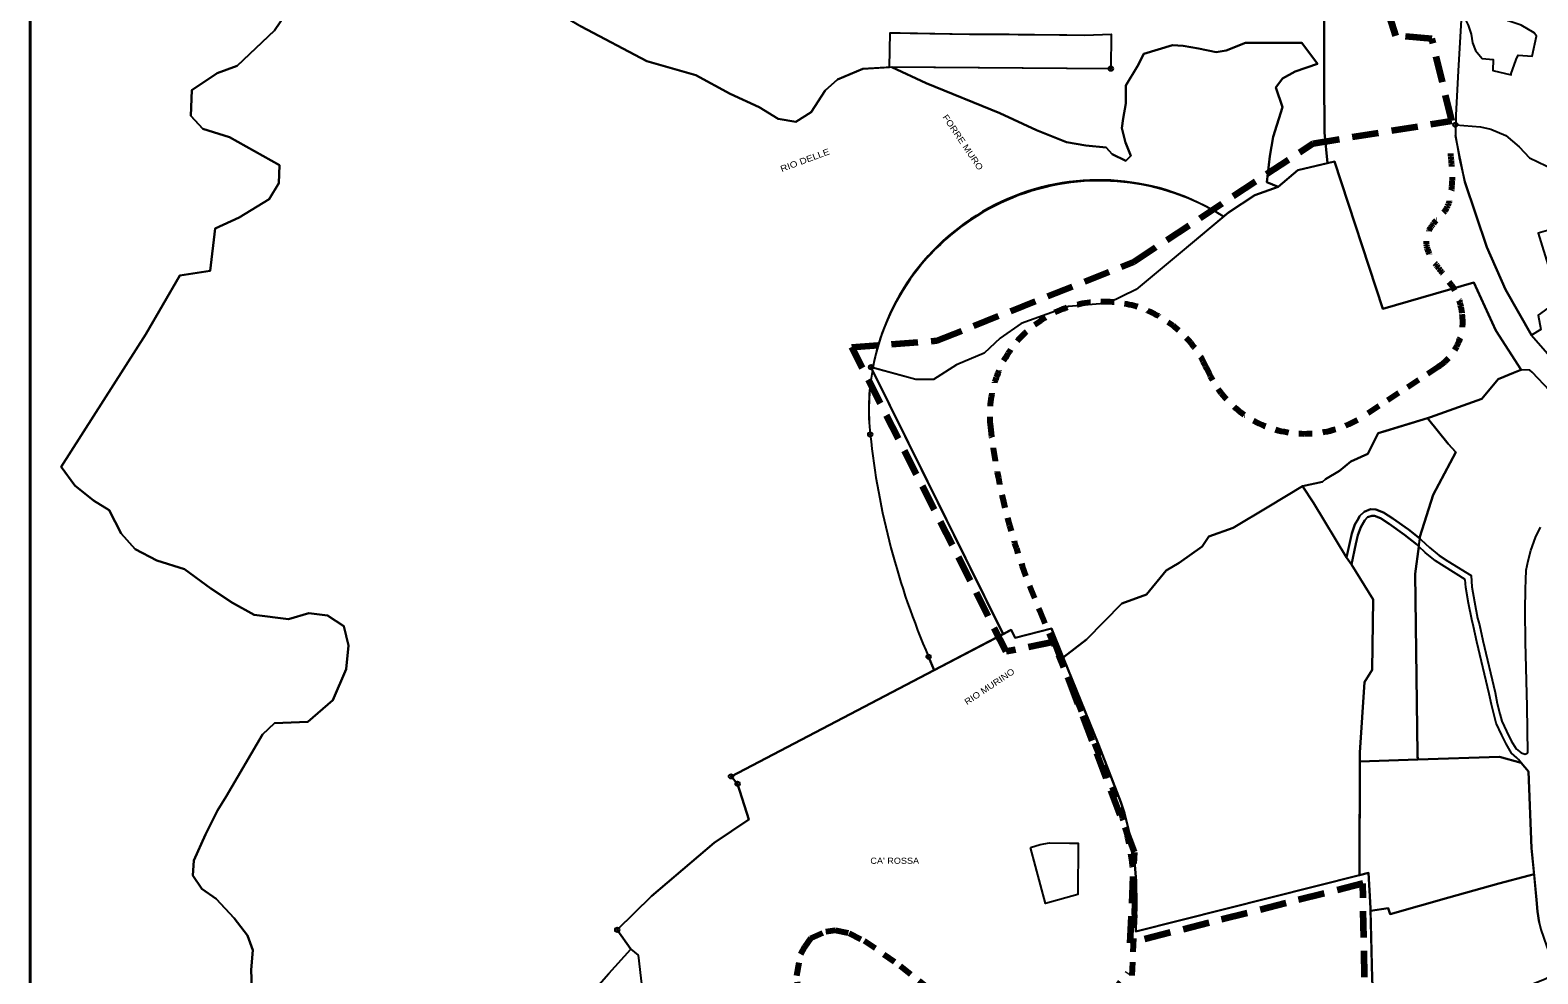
# Model space of a CAD drawing. Extents: x 654952 to 658955, y 890426 to 894481.
# Drawn here: x 657055 to 657738, y 891916 to 892344 of the extents above; entities that cross this region are included whole.
import ezdxf

# ---------------------------------------------------------------- set-up
doc = ezdxf.new("R2010")
doc.units = 0
doc.header["$LTSCALE"] = 4
doc.header["$PDMODE"] = 32
doc.header["$PDSIZE"] = 2
doc.linetypes.add('MEDIUM_DASHED', pattern=[4.5, 3, -1.5])
doc.linetypes.add('SHORT_DASHED', pattern=[2.7, 1.5, -1.2])
for name, color, linetype, lineweight in [('1', 7, 'Continuous', 25), ('12', 7, 'Continuous', 25), ('14', 7, 'Continuous', 25), ('16', 7, 'Continuous', 25), ('18', 7, 'Continuous', 25), ('2', 7, 'Continuous', 25), ('32', 7, 'Continuous', 25), ('35', 7, 'Continuous', 25), ('36', 7, 'Continuous', 25), ('37', 7, 'Continuous', 25), ('41', 7, 'SHORT_DASHED', 80), ('42', 7, 'Continuous', 25), ('43', 7, 'Continuous', 25), ('55', 7, 'Continuous', 25), ('60', 7, 'Continuous', 35), ('7', 7, 'MEDIUM_DASHED', 100), ('9', 7, 'Continuous', 25)]:
    doc.layers.add(name, color=color, linetype=linetype, lineweight=lineweight)
doc.layers.add('58', color=7, linetype='Continuous')

msp = doc.modelspace()

# ---------------------------------------------------------------- linework, layer by layer
at = {"layer": '1'}
for points in [[(657730.31, 892189.89), (657719.89, 892185.61), (657712.47, 892176.68), (657689.22, 892168.43), (657687.88, 892168.02)], [(657743.34, 892180.35), (657735.27, 892188.83), (657734.2, 892189.7), (657730.31, 892189.89)], [(657687.88, 892168.02), (657665.52, 892161.23), (657660.94, 892151.75), (657653.14, 892148.35), (657648.02, 892144.07), (657641.8, 892140.37), (657640.35, 892139.05), (657631.25, 892137.19)], [(657687.88, 892168.02), (657697.26, 892156.31), (657700.7, 892152.54), (657690.55, 892133.19), (657684.5, 892114.14), (657684.4, 892113.38)], [(657684.4, 892113.38), (657684.5, 892114.14), (657690.55, 892133.19), (657700.7, 892152.54), (657697.26, 892156.31), (657687.88, 892168.02)], [(657631.25, 892137.19), (657636.31, 892129.64), (657651.3, 892104.86), (657653.64, 892115.72), (657655, 892119.72), (657656.62, 892122.55), (657657.18, 892123.53)], [(657672.22, 892122.53), (657667.93, 892125.21), (657664.59, 892126.64), (657662.11, 892126.67), (657659.19, 892125.53), (657657.18, 892123.53), (657656.62, 892122.55), (657655, 892119.72), (657653.64, 892115.72), (657651.3, 892104.86), (657653.54, 892101.61)], [(657657.18, 892123.53), (657659.19, 892125.53), (657662.11, 892126.67), (657664.59, 892126.64), (657667.93, 892125.21), (657672.22, 892122.53)], [(657653.54, 892101.61), (657655.49, 892111.05), (657656.44, 892114.9), (657657.67, 892118.52), (657659.51, 892121.74), (657660.81, 892123.04), (657662.64, 892123.75), (657663.98, 892123.74), (657666.58, 892122.62), (657670.61, 892120.11), (657677.56, 892115.18), (657683.14, 892110.66)], [(657672.22, 892122.53), (657679.32, 892117.5), (657684.4, 892113.38)], [(657684.4, 892113.38), (657679.32, 892117.5), (657672.22, 892122.53)], [(657733.42, 892016.41), (657733, 892037.31), (657732.37, 892066.45), (657732.21, 892080.97), (657732.29, 892090.51), (657732.44, 892094.7), (657732.67, 892099.17), (657733.53, 892103.35), (657734.73, 892108.04), (657736.87, 892113.86), (657739.08, 892118.64)], [(657683.14, 892110.66), (657683.96, 892109.9), (657684.4, 892113.38)], [(657684.4, 892113.38), (657685.04, 892112.86), (657688.85, 892109.36), (657693.25, 892105.74), (657697.15, 892103.21), (657707.63, 892096.65), (657707.93, 892091.51)], [(657707.93, 892091.51), (657709.15, 892084.7), (657710.61, 892077.33), (657711.41, 892074.27), (657712.98, 892067.32)], [(657712.98, 892067.32), (657718.58, 892043.66), (657719.49, 892038.78), (657720.74, 892034.1), (657721.54, 892030.67), (657723.63, 892026.19), (657725.88, 892021.79), (657728.09, 892018.11), (657730.39, 892016.38), (657732.08, 892015.83), (657733.42, 892016.41)]]:
    msp.add_lwpolyline(points, dxfattribs=at)
at = {"layer": '12'}
for points in [[(657730.39, 892011.9), (657720.46, 892014.5), (657683.5, 892013.34), (657657.23, 892012.51), (657657.2, 891961.01), (657661.2, 891962.02), (657662.06, 891946.06), (657662.1, 891944.72)], [(657662.1, 891944.72), (657670.04, 891946.05), (657670.95, 891943.35), (657697.64, 891950.84), (657720.22, 891957.11), (657733.98, 891960.82), (657736.18, 891961.41), (657735.02, 891973.19), (657733.61, 892007.87), (657730.39, 892011.9)], [(657736.18, 891961.41), (657733.98, 891960.82), (657720.22, 891957.11), (657697.64, 891950.84), (657670.95, 891943.35), (657670.04, 891946.05), (657662.1, 891944.72)], [(657738.45, 891939.43), (657737.71, 891944.48), (657737.33, 891949.76), (657736.18, 891961.41)], [(657662.1, 891944.72), (657662.89, 891914.18), (657664.35, 891883.16), (657680.65, 891889.73), (657700.14, 891897.46)]]:
    msp.add_lwpolyline(points, dxfattribs=at)
at = {"layer": '14'}
msp.add_line((657720.46, 892014.5), (657730.39, 892011.9), dxfattribs=at)
for points in [[(657683.96, 892109.9), (657683.14, 892110.66), (657677.56, 892115.18), (657670.61, 892120.11), (657666.58, 892122.62), (657663.98, 892123.74), (657662.64, 892123.75), (657660.81, 892123.04), (657659.51, 892121.74), (657657.67, 892118.52), (657656.44, 892114.9), (657655.49, 892111.05), (657653.54, 892101.61), (657663.25, 892085.79), (657662.83, 892053.9), (657659.41, 892048.34), (657657.23, 892016.51), (657657.23, 892012.51), (657683.5, 892013.34)], [(657683.96, 892109.9), (657682.4, 892097.52), (657683.43, 892015.78), (657683.46, 892014.56), (657683.5, 892013.34), (657720.46, 892014.5)], [(657683.5, 892013.34), (657683.46, 892014.56), (657683.43, 892015.78), (657682.4, 892097.52), (657683.96, 892109.9)], [(657705, 892094.85), (657695.58, 892100.75), (657691.53, 892103.39), (657686.94, 892107.16), (657683.96, 892109.9)], [(657730.39, 892011.9), (657729.2, 892013.39), (657728.43, 892014.15), (657726.02, 892016.25), (657723.49, 892020.47), (657721.54, 892024.31), (657718.95, 892029.76), (657718.09, 892033.44), (657716.83, 892038.18), (657715.91, 892043.1), (657710.32, 892066.71), (657708.76, 892073.62), (657707.95, 892076.72), (657706.47, 892084.19), (657705.22, 892091.19), (657705, 892094.85)]]:
    msp.add_lwpolyline(points, dxfattribs=at)
at = {"layer": '16'}
msp.add_line((657648.03, 892144.07), (657653.14, 892148.35), dxfattribs=at)
for points in [[(657730.31, 892189.89), (657718.91, 892207.73), (657708.94, 892229.37), (657667.72, 892217.43), (657645.77, 892284.29), (657629.16, 892280.28), (657620.25, 892272.73), (657609.75, 892268.92), (657597.75, 892261.11), (657575.85, 892242.89), (657556.07, 892226.25), (657543.34, 892220.08), (657525.41, 892218.48), (657503.89, 892210.78), (657494.35, 892204.27), (657487.14, 892197.46), (657474.62, 892192.13), (657464.29, 892185.5), (657456.3, 892185.51), (657435.92, 892191.02), (657495.83, 892070.17), (657499.37, 892072.03), (657501.16, 892068.44), (657517.67, 892072.7), (657523, 892059.5), (657533.55, 892067.71)], [(657687.88, 892168.01), (657689.22, 892168.43), (657712.47, 892176.68), (657719.89, 892185.61), (657726.79, 892188.45), (657729.83, 892189.69), (657730.31, 892189.89)], [(657653.14, 892148.35), (657660.94, 892151.75), (657665.52, 892161.23), (657687.88, 892168.02)], [(657687.88, 892168.01), (657687.88, 892168.02), (657665.52, 892161.23)], [(657665.52, 892161.23), (657669.19, 892162.16), (657687.88, 892168.01)], [(657533.55, 892067.71), (657549.56, 892083.97), (657560.65, 892088.04), (657569.61, 892099.03), (657575.43, 892102.47), (657585.94, 892109.88), (657588.88, 892114.41), (657599.93, 892118.21), (657616.11, 892127.89), (657631.25, 892137.19), (657640.35, 892139.05)], [(657640.35, 892139.05), (657641.8, 892140.37), (657648.02, 892144.07)], [(657631.25, 892137.19), (657616.11, 892127.89), (657599.93, 892118.21), (657588.88, 892114.41), (657585.94, 892109.88), (657575.43, 892102.47), (657569.61, 892099.03), (657560.65, 892088.04), (657549.56, 892083.97), (657533.55, 892067.71), (657523, 892059.5)], [(657657.2, 891961.01), (657657.23, 892016.51), (657659.41, 892048.34), (657662.83, 892053.9), (657663.26, 892085.79), (657653.54, 892101.61), (657651.3, 892104.86), (657636.31, 892129.64), (657631.25, 892137.19)], [(657523, 892059.5), (657538.92, 892020.11), (657549.05, 891994.02), (657550.72, 891989.05), (657552.37, 891982.35), (657554.39, 891973.09), (657555.19, 891967.45), (657555.96, 891958.26), (657556.12, 891947.47), (657555.83, 891935.5), (657657.2, 891961.01)]]:
    msp.add_lwpolyline(points, dxfattribs=at)
at = {"layer": '18'}
for points in [[(657544.51, 892326.27), (657544.51, 892326.27), (657444.35, 892326.94), (657444.6, 892342.44)], [(657444.6, 892342.44), (657449.13, 892342.44), (657480.5, 892341.94), (657498.5, 892341.94), (657532.75, 892341.44), (657544.73, 892341.91), (657544.51, 892326.27)]]:
    msp.add_lwpolyline(points, dxfattribs=at)
msp.add_point((657544.51, 892326.27), dxfattribs=at)
at = {"layer": '2'}
msp.add_lwpolyline([(657508.14, 891973.49), (657512.53, 891974.91), (657516.71, 891975.52), (657525.85, 891975.44), (657529.78, 891975.4), (657529.57, 891952.22), (657515, 891948.05)], close=True, dxfattribs=at)
at = {"layer": '32'}
for points in [[(657499.37, 892072.03), (657495.87, 892070.2), (657372.54, 892005.7), (657375.54, 892002.31), (657380.61, 891986.11), (657364.98, 891975.6), (657336.53, 891951.39), (657321.01, 891936.2), (657327.2, 891927.48), (657330.48, 891924.75), (657333.71, 891897.41)], [(657657.2, 891961.01), (657555.83, 891935.5), (657556.12, 891947.47), (657555.96, 891958.26), (657555.19, 891967.45), (657554.39, 891973.09), (657552.37, 891982.35), (657550.72, 891989.05), (657549.05, 891994.02), (657538.92, 892020.11), (657517.67, 892072.7), (657501.16, 892068.44), (657499.37, 892072.03)], [(657680.65, 891889.73), (657680.65, 891889.73), (657664.35, 891883.16), (657662.89, 891914.18), (657662.06, 891946.06), (657661.2, 891962.02), (657657.2, 891961.01)]]:
    msp.add_lwpolyline(points, dxfattribs=at)
at = {"layer": '35'}
msp.add_lwpolyline([(657333.71, 891897.41), (657331.73, 891853.22), (657356.3, 891845.74), (657368.76, 891841.68), (657396.27, 891828.43), (657328.24, 891714.82), (657314.28, 891707.1), (657284.74, 891693.21), (657234.36, 891722), (657211.1, 891732.13), (657198.81, 891740.15), (657211.6, 891767.49), (657221.37, 891781.04), (657236.78, 891798.07), (657250.85, 891807.99), (657281.25, 891827.07), (657299.59, 891838.23), (657313.17, 891849.32), (657311.41, 891867.55), (657311.06, 891883.8), (657310.62, 891908.79), (657317.2, 891916.42), (657327.2, 891927.48), (657330.48, 891924.75)], close=True, dxfattribs=at)
at = {"layer": '36'}
for p, q in [((657436.55, 892189.74), (657435.96, 892191.05)), ((657375.53, 892002.31), (657372.54, 892005.7))]:
    msp.add_line(p, q, dxfattribs=at)
for points in [[(657183.78, 892370.19), (657165.83, 892343.58), (657148.87, 892327.61), (657139.89, 892324.23), (657128.42, 892316.49), (657127.92, 892304.87), (657133.41, 892299.07), (657145.38, 892295.2), (657168.06, 892282.53), (657167.79, 892274.35), (657163.34, 892267.13), (657149.87, 892258.91), (657138.92, 892253.91), (657136.67, 892234.74), (657122.96, 892232.62), (657107.49, 892206.01), (657069.15, 892145.94), (657075.42, 892137.49), (657083.86, 892130.68), (657090.95, 892126.31), (657096.4, 892115.68), (657102.66, 892108.59), (657112.47, 892103.41), (657125, 892099.59), (657136.99, 892090.86), (657146.8, 892084.32), (657156.61, 892078.87), (657172.14, 892076.96), (657181.4, 892079.69), (657189.85, 892078.6), (657197.21, 892073.69), (657199.39, 892064.96)], [(657551.31, 892310.56), (657550.05, 892303.77), (657549.54, 892299.3), (657551.22, 892292.76), (657553.62, 892286.83), (657551.25, 892284.56), (657545.19, 892287.54), (657542.43, 892290.55), (657533.22, 892291.46), (657524.43, 892292.96), (657510.86, 892298.49), (657494.34, 892306.19), (657460.93, 892319.77), (657445.29, 892326.9), (657432.24, 892326.27), (657420.77, 892321.44), (657415.15, 892316.34), (657408.87, 892306.53), (657401.84, 892302.26), (657393.84, 892303.53), (657385.36, 892308.86), (657372.19, 892314.83), (657356.62, 892323.38), (657334.42, 892329.69), (657304.73, 892345.36)], [(657572.41, 892336.96), (657559.4, 892333.03), (657556.58, 892327.41), (657551.31, 892318.61), (657551.31, 892310.56)], [(657595.52, 892259.25), (657597.75, 892261.11), (657609.75, 892268.92), (657620.25, 892272.73), (657615.22, 892274.91), (657616.59, 892286.63), (657618.09, 892295.34), (657622.33, 892308.89), (657619.3, 892317.82), (657622.29, 892321.87), (657627.99, 892325.02), (657638.11, 892328.52), (657630.99, 892338.02), (657605.49, 892338.02), (657596.74, 892334.52), (657592.26, 892333.68), (657584.22, 892335.44), (657577.28, 892336.58), (657572.41, 892336.96)], [(657435.96, 892191.05), (657436.75, 892190.8), (657439.2, 892201.06)], [(657199.39, 892064.96), (657198.3, 892054.33), (657192.3, 892040.15), (657180.86, 892030.34), (657165.87, 892029.79), (657160.38, 892024.64), (657143.92, 891996.57), (657139.97, 891990.26), (657134.52, 891979.35), (657129.34, 891967.63), (657128.8, 891960.81), (657132.89, 891954.81), (657139.43, 891950.18), (657147.6, 891941.45), (657153.59, 891933.55), (657156.05, 891927), (657155.23, 891918), (657155.5, 891910.1)], [(657372.54, 892005.7), (657464.5, 892053.79), (657462, 892059.9)], [(657321.01, 891936.2), (657336.53, 891951.39), (657364.98, 891975.6), (657380.61, 891986.11), (657375.53, 892002.31)], [(657310.62, 891908.79), (657317.2, 891916.42), (657327.2, 891927.48), (657321.01, 891936.2)]]:
    msp.add_lwpolyline(points, dxfattribs=at)
for centre, radius, start, end in [((657539.49, 892170.71), 104.78, 57.6754, 163.16084), ((657533.63, 892171.89), 98.71, 169.5784, 186.57047), ((657776.92, 892196.36), 343.22, 185.98257, 203.42742)]:
    msp.add_arc(centre, radius, start, end, dxfattribs=at)
for p in [(657435.96, 892191.05), (657435.57, 892160.59), (657462, 892059.9), (657372.54, 892005.7), (657375.53, 892002.31), (657321.01, 891936.2)]:
    msp.add_point(p, dxfattribs=at)
at = {"layer": '37'}
for points in [[(657200.09, 892496.84), (657205.37, 892485.03), (657205.87, 892476.23), (657204.37, 892465.67), (657202.36, 892454.61), (657204.12, 892440.53), (657210.15, 892427.46), (657221.7, 892409.61), (657240.29, 892385.98), (657265.18, 892368.72), (657304.73, 892345.36), (657334.42, 892329.69), (657356.62, 892323.38), (657372.19, 892314.83), (657385.36, 892308.86), (657393.84, 892303.53), (657401.84, 892302.26), (657408.87, 892306.53), (657415.15, 892316.34), (657420.77, 892321.44), (657432.24, 892326.27), (657444.35, 892326.94)], [(657642.61, 892283.53), (657641.27, 892297.38), (657641.13, 892322.31), (657641.13, 892364.6), (657640.7, 892377.37), (657633.78, 892380.66), (657615.95, 892385.78), (657610.51, 892385.78), (657610.01, 892393.05), (657607.54, 892403.45), (657599, 892407.44), (657599.5, 892383.44)], [(657096.4, 892115.68), (657090.95, 892126.31), (657083.86, 892130.68), (657075.42, 892137.49), (657069.15, 892145.94), (657107.49, 892206.01), (657122.96, 892232.62), (657136.67, 892234.74), (657138.92, 892253.91), (657149.87, 892258.91), (657163.34, 892267.13), (657167.79, 892274.35), (657168.06, 892282.53), (657145.38, 892295.2), (657133.41, 892299.07), (657127.92, 892304.87), (657128.42, 892316.49), (657139.89, 892324.23), (657148.87, 892327.61), (657165.83, 892343.58), (657183.78, 892370.19)], [(657444.35, 892326.94), (657444.6, 892342.44), (657480.5, 892341.94), (657524.55, 892341.64), (657532.75, 892341.44), (657544.73, 892341.91), (657544.51, 892326.27), (657544.51, 892326.27), (657445.29, 892326.9), (657460.93, 892319.77), (657494.34, 892306.19), (657510.86, 892298.49), (657524.43, 892292.96), (657533.22, 892291.46), (657542.43, 892290.55), (657545.19, 892287.54), (657551.25, 892284.56), (657553.62, 892286.83), (657551.22, 892292.76), (657549.54, 892299.3)], [(657551.31, 892310.56), (657551.31, 892318.61), (657556.58, 892327.41), (657559.4, 892333.03), (657572.41, 892336.96), (657577.28, 892336.58), (657584.22, 892335.44), (657592.26, 892333.68), (657596.74, 892334.52), (657605.49, 892338.02), (657630.99, 892338.02), (657638.11, 892328.52), (657627.99, 892325.02), (657622.29, 892321.87), (657619.3, 892317.82), (657622.33, 892308.89), (657618.09, 892295.34), (657616.59, 892286.63), (657615.22, 892274.91)], [(657549.54, 892299.3), (657550.05, 892303.77), (657551.31, 892310.56)], [(657615.22, 892274.91), (657620.25, 892272.73), (657629.16, 892280.28), (657642.61, 892283.53)], [(657155.5, 891910.1), (657155.23, 891918), (657156.05, 891927), (657153.59, 891933.55), (657147.6, 891941.45), (657139.43, 891950.18), (657132.89, 891954.81), (657128.8, 891960.81), (657129.34, 891967.63), (657134.52, 891979.35), (657139.97, 891990.26), (657143.92, 891996.57), (657160.38, 892024.64), (657165.87, 892029.79), (657180.86, 892030.34), (657192.3, 892040.15), (657198.3, 892054.33), (657199.39, 892064.96), (657197.21, 892073.69), (657189.85, 892078.6), (657181.4, 892079.69), (657172.14, 892076.96), (657156.61, 892078.87), (657146.8, 892084.32), (657136.99, 892090.86), (657125, 892099.59), (657112.47, 892103.41), (657102.66, 892108.59), (657096.4, 892115.68)]]:
    msp.add_lwpolyline(points, dxfattribs=at)
at = {"layer": '41'}
for p, q in [((657692.89, 892191.33), (657658.17, 892168.4)), ((657512.43, 892080.57), (657545.13, 892000.77)), ((657555.25, 891943.05), (657553.12, 891893.42))]:
    msp.add_line(p, q, dxfattribs=at)
msp.add_lwpolyline([(657423.73, 891844.49), (657420.07, 891852.62), (657411.04, 891879.73), (657403.6, 891906.76), (657402.28, 891915.56), (657404.14, 891925.22), (657405.93, 891928.5), (657408.66, 891932.36), (657415.4, 891935.36), (657419.68, 891936.02), (657426, 891934.67), (657432.83, 891931.25), (657449.12, 891919.85), (657468.6, 891904.5), (657483.88, 891893.88), (657493.84, 891889.55), (657501.99, 891886.66), (657508.61, 891886.39), (657524.72, 891889.08), (657538.62, 891899.4), (657552.24, 891916.91)], dxfattribs=at)
for centre, radius, start, end in [((657678.39, 892213.33), 25.26, 5.12622, 39.89881), ((657541.11, 892169.31), 51.4, 24.31576, 184.72431), ((657679.71, 892211.61), 24.19, 302.91893, 10.44917), ((657632.4, 892209.14), 48.21, 202.62351, 302.321), ((657776.93, 892196.37), 288.74, 186.1982, 203.64305), ((657418.91, 891948.9), 136.46, 357.54561, 22.34334)]:
    msp.add_arc(centre, radius, start, end, dxfattribs=at)
msp.add_open_spline([(657698.28, 892287.91), (657698.28, 892287.89), (657698.75, 892282.89), (657699.33, 892274.85), (657697.63, 892262.6), (657691.39, 892257.4), (657687.87, 892252.6), (657686.76, 892245.78), (657690.03, 892239.64), (657694.2, 892234.29), (657696.65, 892231.04), (657697.91, 892229.35)], degree=3, dxfattribs=at)
at = {"layer": '42'}
msp.add_line((657462, 892059.9), (657464.5, 892053.79), dxfattribs=at)
for points in [[(657595.52, 892259.25), (657575.85, 892242.89), (657556.07, 892226.25), (657543.34, 892220.08), (657525.41, 892218.48), (657503.89, 892210.78), (657494.35, 892204.27), (657487.14, 892197.46), (657474.62, 892192.13), (657464.29, 892185.5), (657456.3, 892185.51), (657436.75, 892190.8)], [(657464.5, 892053.79), (657495.83, 892070.18), (657436.55, 892189.74)]]:
    msp.add_lwpolyline(points, dxfattribs=at)
for centre, radius, start, end in [((657539.12, 892171.7), 104.15, 57.21297, 169.43431), ((657539.12, 892171.7), 104.15, 170.02491, 186.12396), ((657776.92, 892196.36), 343.22, 185.98257, 203.42742)]:
    msp.add_arc(centre, radius, start, end, dxfattribs=at)
at = {"layer": '43'}
msp.add_lwpolyline([(657703.61, 892356.05), (657701.75, 892325.28), (657700.74, 892305.16), (657700.57, 892296.04), (657702.26, 892286.06), (657704.79, 892275.08), (657714.76, 892245.49), (657723.21, 892226.22), (657735.04, 892205.6), (657752.77, 892185.16), (657763.24, 892167.58), (657763.92, 892156.25), (657757.41, 892135.8), (657768.46, 892136), (657777.91, 892134.81), (657785.14, 892135.71), (657793.71, 892140.15), (657799.95, 892138.82), (657806.18, 892137.49), (657813.16, 892149.6), (657813.62, 892151.58)], dxfattribs=at)
at = {"layer": '55'}
for points in [[(657640.7, 892377.37), (657641.13, 892364.6), (657641.13, 892322.31), (657641.27, 892297.38), (657642.61, 892283.53)], [(657642.61, 892283.53), (657645.77, 892284.29), (657667.72, 892217.43), (657708.94, 892229.37), (657718.91, 892207.73), (657730.31, 892189.89), (657729.83, 892189.69)], [(657729.83, 892189.69), (657726.79, 892188.45), (657719.89, 892185.61), (657712.47, 892176.68), (657689.22, 892168.43), (657687.89, 892168.01)], [(657687.89, 892168.01), (657697.26, 892156.31), (657700.7, 892152.54), (657690.55, 892133.19), (657684.5, 892114.14), (657682.4, 892097.52), (657683.43, 892015.78), (657683.5, 892013.34)], [(657683.5, 892013.34), (657720.46, 892014.5), (657730.39, 892011.9), (657733.61, 892007.87), (657735.02, 891973.19), (657737.33, 891949.76)], [(657737.33, 891949.76), (657737.71, 891944.48), (657738.45, 891939.43), (657739.24, 891936.31), (657741.82, 891928.98), (657742.96, 891925.58), (657743.11, 891920.79), (657744.38, 891915.57), (657740.93, 891913.75), (657700.14, 891897.46)]]:
    msp.add_lwpolyline(points, dxfattribs=at)
at = {"layer": '60', "lineweight": 40}
msp.add_lwpolyline([(657055.17, 894480.74), (658955.28, 894480.74), (658955.28, 890425.88), (657055.17, 890425.88)], close=True, dxfattribs=at)
at = {"layer": '7'}
msp.add_lwpolyline([(657660.12, 891878.68), (657658.62, 891957.13), (657553.31, 891930.32), (657555.21, 891971.29), (657519.02, 892066.59), (657497.19, 892062.2), (657427.26, 892200.13), (657465.85, 892203.1), (657554.9, 892238.74), (657636.17, 892292.45), (657698.87, 892302.6), (657689.96, 892339.72), (657673.64, 892341.21), (657661.76, 892378.34)], dxfattribs=at)
at = {"layer": '9'}
msp.add_lwpolyline([(657703.21, 892350.58), (657704.87, 892348.94), (657706.37, 892345.94), (657707.63, 892341.94), (657708.37, 892337.94), (657709.63, 892334.44), (657712.75, 892330.94), (657717.63, 892330.44), (657717.5, 892325.44), (657725.75, 892323.44), (657725.62, 892323.62), (657728.13, 892330.44), (657729, 892332.44), (657735.37, 892331.94), (657737.25, 892340.94), (657736.25, 892342.44), (657730.37, 892345.94), (657724.5, 892347.94), (657720.5, 892350.94), (657716.4, 892350.82), (657710.87, 892357.44), (657708.13, 892356.94), (657706.37, 892355.94), (657705.25, 892354.44)], close=True, dxfattribs=at)
msp.add_lwpolyline([(657700.56, 892300.88), (657711.87, 892299.94), (657716.63, 892298.94), (657723.37, 892295.94), (657729.5, 892290.94), (657734.13, 892285.94), (657745.37, 892280.44), (657749.87, 892275.94), (657754.78, 892255.81), (657747.5, 892254.44), (657738.08, 892251.71), (657747.43, 892221.45), (657737.96, 892214.62), (657739.29, 892208.08), (657735.04, 892205.6), (657723.21, 892226.22), (657714.76, 892245.49), (657704.79, 892275.08), (657700.57, 892296.04)], dxfattribs=at)
msp.add_point((657700.56, 892300.88), dxfattribs=at)

# ---------------------------------------------------------------- texts
at = {"layer": '58'}
for s, height, rotation, width, p in [('FORRE MURO', 2.797, 303.956, 1.15, (657468.17, 892304.33)), ('RIO DELLE', 2.801, 20.406, 1.2, (657395.5, 892279.42)), ('RIO MURINO', 2.799, 33.734, 1.15, (657479.4, 892037.91))]:
    msp.add_text(s, height=height, rotation=rotation, dxfattribs=dict(at, width=width)).set_placement(p)
at = {"layer": '58', "width": 1.1}
msp.add_text("CA' ROSSA", height=2.801, dxfattribs=at).set_placement((657435.63, 891966.08))

doc.saveas('drawing.dxf')
